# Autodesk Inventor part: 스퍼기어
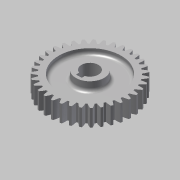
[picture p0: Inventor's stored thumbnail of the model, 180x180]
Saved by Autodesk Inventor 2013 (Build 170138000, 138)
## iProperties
Created: 2013-08
Part Number: 스퍼기어
Material: 강
Document SubType Name: Modeling
Designer: 한국산업디자인학원
Categories: <?xml version="1.0" encoding="UTF-16"?> <MemberInstance><Categories><FamilyTemplate><FamilyTemplateParameter ValueType="xs:double" Id="1" ObjectReferenceKey="da
Density: 1 g/cm^3
CustomPartVersion: 1
Author: 한국산업디자인학원
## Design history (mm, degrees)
sketch "Sketch1"
  geometry: C1 r 37 at (0, 0)
  constraints: 1 centre point
  dimensions: "d0" = 74 diameter of C1 (= da_da)
extrude "Extrusion1" new body sketch "Sketch1" distance "d1" = 15 (= da_b); taper "d2" = 0 deg
workplane "Work Plane2"
feature "피치 지름" dims "d4" = 10, "d5" = 0
workplane "Work Plane8"
workplane "Work Plane9"
feature "스퍼 기어" dims "da_b" = 15, "da_d" = 70, "da_aw" = 70, "da_da" = 74, "da_df" = 65, "da_dw" = 70, angle "da_beta" = 0 deg, "da_lefttooth" = 0, "da_righttooth" = 0
node "작업 평면11"
sketch "스케치4"
  geometry: C1 r 12.5 at (0, 0); C2 r 7.5 at (0, 0); 1 further point
  constraints: 2 centre point, 2 coincident
  dimensions: "d50" = 25 diameter of C1; "d51" = 15 diameter of C2
extrude "돌출2" join sketch "스케치4" distance "d52" = 31; taper "d53" = 0 deg
hole "구멍1" diameter "d56" = 15; stored, may be unused: countersink angle "d60" = 90 deg, drill point angle "d62" = 118 deg; dims "d54" = 10, "d55" = 10, "d57" = 6, "d58" = 4, "d59" = 2, "d61" = 8
sketch "스케치5"
  geometry: C1 r 12.5 at (0, 0) reference; C2 r 27.5 at (0, 0)
  constraints: 1 centre point, 1 coincident
  dimensions: "d63" = 55 diameter of C2
extrude "돌출3" cut sketch "스케치5" distance "d64" = 5; taper "d65" = 0 deg
sketch "스케치6"
  geometry: C1 r 12.5 at (0, 0) reference; C2 r 27.5 at (0, 0)
  constraints: 1 centre point, 1 coincident
  dimensions: "d66" = 55 diameter of C2
extrude "돌출4" cut sketch "스케치6" distance "d67" = 5; taper "d68" = 0 deg
sketch "스케치7"
  geometry: L1 (-7.5, 18)-(7.5, 18) reference; L2 (2.5, 18)-(-2.5, 18); L3 (-2.5, 18)-(-2.5, -13); L4 (-2.5, -13)-(2.5, -13); L5 (2.5, -13)-(2.5, 18); L6 (7.5, -13)-(-7.5, -13) reference; 3 further points
  constraints: 8 end point, 4 midpoint, 2 parallel, 1 coincident, 1 horizontal, 1 perpendicular
  dimensions: "d69" = 5 distance between parallel lines of L3 L5
extrude "돌출5" cut sketch "스케치7" distance "d71" = 9.8; taper "d72" = 0 deg
fillet "모깎기1" dims "d73" = 3
body "Solid1"
sketch "Sketch2"
  geometry: C1 r 37 at (0, 0) reference; C2 r 35 at (0, 0)
  constraints: 1 centre point, 1 coincident
  dimensions: "d3" = 70 diameter of C2 (= da_dw)
body "Srf1"
other parameters: "d17" = 0, "d34" = 0.8976 (computed from da_z), "d39" = 0, "d41" = 0, "d47" = 0, "d48" = 0, "d49" = 3
